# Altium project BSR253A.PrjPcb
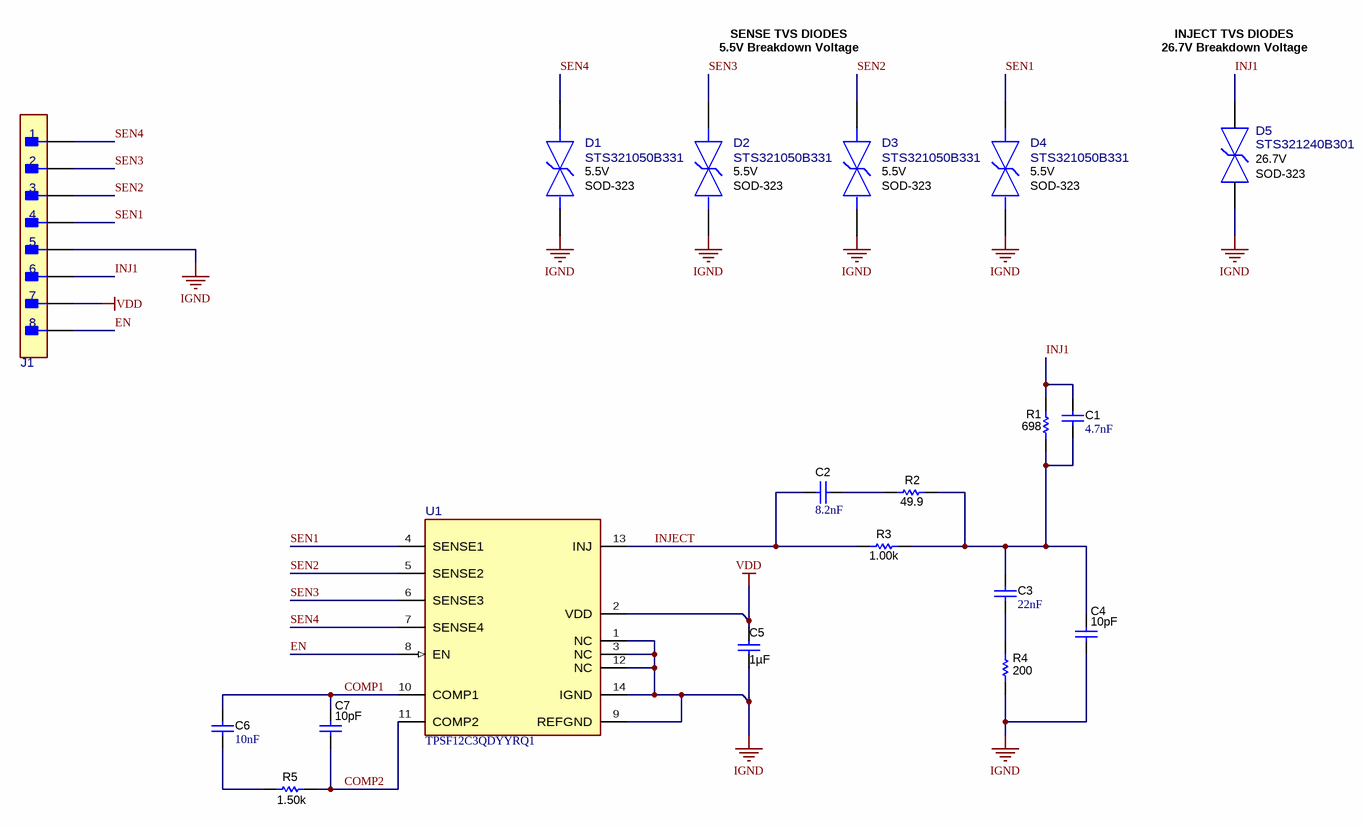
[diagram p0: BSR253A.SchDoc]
DrawnBy: Tony Jacobs; PCB_Rev: A; PRJ_Customer: TBD; PRJ_Engineer: Timothy Hegarty; PRJ_Number: BSR253; PRJ_Title: TPSF12C3QEVM; SCH_Rev: A; TechSupport: TBD; TID: N/A; title: Daughter Card Schematic
2 sheets, 29 parts. Net scope: global (net labels, ports and power ports of the same name join across sheets).
Board file: BSR253A.PcbDoc
Sheets:
  BSR253A.SchDoc
  BSR253A HW.SchDoc

## Sheet BSR253A.SchDoc: Daughter Card Schematic
size A3; Date: Not shown in title block; ApprovedBy: Not shown in title block; CheckedBy: Not shown in title block; Author: Not shown in title block; CompanyName: Not shown in title block; DrawnBy: Tony Jacobs; Engineer: Not shown in title block; Organization: Not shown in title block; Address1: Not shown in title block; Address2: Not shown in title block; Address3: Not shown in title block; Address4: Not shown in title block; DocumentNumber: 1; Revision: Use project parameter SCH_Rev; SheetNumber: 1; SheetTotal: 2; PageSetup: Record=PageOptions¦CenterHorizontal=True¦CenterVertical=True¦PrintScale=0.93¦XCorrection=1.00¦YCorrection=1.00¦PrintKind=0¦BorderSize=5000000¦LeftOffset=0¦BottomOffset=0¦Orientation=2¦PaperLength=1000¦PaperWidth=1000¦Scale=100¦PaperSource=15¦PrintQuality=600¦MediaType=1¦DitherType=10¦PrintScaleMode=1¦PaperKind=Letter

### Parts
C1  Cap_F: 4.7nF  [0603L]  (hidden comment: C0603C472J5RACTU)
C2  Cap_F: 8.2nF  [0603L]  (hidden comment: GCD188R71H822KA01D)
C3  Cap_F: 22nF  [0603L]  (hidden comment: C0603C223K5RACTU)
C4  value 10pF  [0603L]  (hidden comment: CGA3E2C0G1H100D080AA)
C5  Cap_F: 1µF  [0603L]  (hidden comment: CGA3E1X7R1E105K080AC)
C6  Cap_F: 10nF  [0603L]  (hidden comment: C0603X103K5RACTU)
C7  ValueDisplayed: 10pF  [0603L]  (hidden comment: CGA3E2C0G1H100D080AA)
D1  STS321050B331  PackageReference: SOD-323  Breakdown Voltage: 5.5V  [FP-STS321050B331_SOD-323-MFG]
D2  STS321050B331  PackageReference: SOD-323  Breakdown Voltage: 5.5V  [FP-STS321050B331_SOD-323-MFG]
D3  STS321050B331  PackageReference: SOD-323  Breakdown Voltage: 5.5V  [FP-STS321050B331_SOD-323-MFG]
D4  STS321050B331  PackageReference: SOD-323  Breakdown Voltage: 5.5V  [FP-STS321050B331_SOD-323-MFG]
D5  STS321240B301  PackageReference: SOD-323  Breakdown Voltage: 26.7V  [FP-STS321240B301_SOD-323-MFG]
J1  TSW-108-08-G-S-RA  [FP-TSW-108-08-G-S-RA_HDR8-MFG]  (value not drawn)
R1  ValueDisplayed: 698  [0603L]  (hidden comment: CRCW0603698RFKEA)
R2  ValueDisplayed: 49.9  [0603L]  (hidden comment: CRCW060349R9FKEA)
R3  ValueDisplayed: 1.00k  [0603L]  (hidden comment: CRCW06031K00FKEA)
R4  ValueDisplayed: 200  [0603L]  (hidden comment: CRCW0603200RFKEA)
R5  ValueDisplayed: 1.50k  [0603L]  (hidden comment: CRCW06031K50FKEA)
U1  TPSF12C3QDYYRQ1  [DYY0014A-MFG]

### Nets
IGND: C4.1 C5.2 D1.2 D2.2 D3.2 D4.2 D5.2 J1.5 R4.1 U1.1(NC) U1.3(NC) U1.9(REFGND) U1.12(NC) U1.14(IGND)
VDD: C5.1 J1.7 U1.2(VDD)
COMP1: C6.2 C7.2 U1.10(COMP1)
COMP2: C7.1 R5.2 U1.11(COMP2)
EN: J1.8 U1.8(EN)
INJ1: C1.2 D5.1 J1.6 R1.2
INJECT: C2.1 R3.1 U1.13(INJ)
SEN1: D4.1 J1.4 U1.4(SENSE1)
SEN2: D3.1 J1.3 U1.5(SENSE2)
SEN3: D2.1 J1.2 U1.6(SENSE3)
SEN4: D1.1 J1.1 U1.7(SENSE4)
NetC1_1: C1.1 C3.1 C4.2 R1.1 R2.2 R3.2
NetC2_2: C2.2 R2.1
NetC3_2: C3.2 R4.2
NetC6_1: C6.1 R5.1

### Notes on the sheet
- SENSE TVS DIODES
- 5.5V Breakdown Voltage
- INJECT TVS DIODES
- 26.7V Breakdown Voltage

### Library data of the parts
C1 = CMP-0006942-1: CAP, CERM, 4700 pF, 50 V, +/- 5%, X7R, 0603; Manufacturer: Kemet; TaMin_C: -55°C; Polarized: N; SizeAreaWB_mm2: 4.68; Value1: Unknown; U/M: EA; Value: 4700pF; TaMax_C: 125°C; SizeZ_mm: 1; SizeX_mm: 1.6; SizeY_mm: 0.8; Cap_Case: 0603; Value2: 50V; SizeArea_mm2: 1.28; AEC Category: Q200
C2 = CMP-0007123-4: CAP, CERM, 8200 pF, 50 V, +/- 10%, X7R, AEC-Q200 Grade 1, 0603; Manufacturer: MuRata; TaMin_C: -55°C; Polarized: N; SizeAreaWB_mm2: 4.68; Value1: Unknown; U/M: EA; Value: 8200pF; TaMax_C: 125°C; SizeZ_mm: 1; SizeX_mm: 1.6; SizeY_mm: 0.8; Cap_Case: 0603; Value2: 50V; SizeArea_mm2: 1.28; AEC Qualified: Y; AEC Category: Q200
C3 = CMP-0006901-4: CAP, CERM, 0.022 uF, 50 V, +/- 10%, X7R, 0603; Manufacturer: Kemet; TaMin_C: -55°C; Polarized: N; Value1: Unknown; U/M: EA; TaMax_C: 125°C; SizeAreaWB_mm2: 4.68; SizeZ_mm: 1; SizeX_mm: 1.6; SizeY_mm: 0.8; Cap_Case: 0603; Value2: 50V; SizeArea_mm2: 1.28; AEC Category: Q200
C4 = CMP-0007069-4: CAP, CERM, 10 pF, 50 V, +/- 5%, C0G/NP0, AEC-Q200 Grade 1, 0603; Manufacturer: TDK; TaMin_C: -55°C; Polarized: N; SizeAreaWB_mm2: 4.68; Value1: Unknown; U/M: EA; TaMax_C: 125°C; SizeZ_mm: 1; SizeX_mm: 1.6; SizeY_mm: 0.8; Cap_Case: 0603; Value2: 50V; SizeArea_mm2: 1.28; AEC Qualified: Y; AEC Category: Q200
C5 = CMP-0076705-3: CAP, CERM, 1 µF, 25 V,+/- 10%, X7R, AEC-Q200 Grade 1, 0603; Manufacturer: TDK; SizeAreaWB_mm2: 4.68; SizeArea_mm2: 1.28; AEC Qualified: Y; AEC Category: Q200; Value: 1uF; TaMax_C: 125°C; SizeZ_mm: 1.0; AEC Grade: 1; Polarized: N; TaMin_C: -55°C; VDC_V: 25V; SizeY_mm: 0.8; U/M: EA; SizeX_mm: 1.6; Cap_Case: 1.6x0.8x0.8mm
C6 = CMP-0006978-1: CAP, CERM, 0.01 uF, 50 V, +/- 10%, X7R, 0603; Manufacturer: Kemet; TaMin_C: -55°C; Polarized: N; SizeAreaWB_mm2: 4.68; Value1: Unknown; U/M: EA; Value: 0.01uF; TaMax_C: 125°C; SizeZ_mm: 1; SizeX_mm: 1.6; SizeY_mm: 0.8; Cap_Case: 0603; Value2: 50V; SizeArea_mm2: 1.28; AEC Category: Q200
C7 = CMP-0007069-4: CAP, CERM, 10 pF, 50 V, +/- 5%, C0G/NP0, AEC-Q200 Grade 1, 0603; Manufacturer: TDK; TaMin_C: -55°C; Polarized: N; SizeAreaWB_mm2: 4.68; Value1: Unknown; U/M: EA; Value: 10pF; TaMax_C: 125°C; SizeZ_mm: 1; SizeX_mm: 1.6; SizeY_mm: 0.8; Cap_Case: 0603; Value2: 50V; SizeArea_mm2: 1.28; AEC Qualified: Y; AEC Category: Q200
D1-D4 = CMP-0092592-1: 18V Clamp 22A (8/20µs) Ipp Tvs Diode Surface Mount SOD-323; Manufacturer: Eaton; Cap_F: 33pF; Number Of Channels: 1; SizeZ_mm: 1mm; AEC Qualified: No; Ppk: 400W; VRWM: 5V; TJmax_C: +125°C; Direction: Bidirectional
D5 = CMP-0092593-1: 50V Clamp 8A (8/20µs) Ipp Tvs Diode Surface Mount SOD-323; Manufacturer: Eaton; VRWM: 24V; Ppk: 400W; ValueDisplayed: 40pF; Standoff Height: 0mm; SizeZ_mm: 1mm; Direction: Bidirectional; TJmax_C: +125°C; AEC Qualified: No; Number Of Channels: 1
J1 = CMP-0097195-1: Manufacturer: Samtec; AEC Qualified: No; Conn Gender: Male; SizeZ_mm: 3.15mm; ContactFinish: Gold,Nickel; DUT-Pitch_mm: 2.54mm; Row_Count: 1; Conn Orientation: Right Angle
R1 = CMP-0022555-5: RES, 698, 1%, 0.1 W, AEC-Q200 Grade 0, 0603; Manufacturer: Vishay-Dale; Power_W: 100mW; TempCo: 100 ppm/C; Value_Code: 698R; Value: 698; EIA_Code: E96; SizeX_mm: 1.6; SizeY_mm: 0.8; SizeZ_mm: 1; Value2: 0.1W; SizeArea_mm2: 1.28; AEC Qualified: Y; VDC_V: 75V; AEC Category: Q200; AEC Grade: 0
R2 = CMP-0022448-4: RES, 49.9, 1%, 0.1 W, AEC-Q200 Grade 0, 0603; Manufacturer: Vishay-Dale; Power_W: 100mW; TempCo: 100 ppm/C; Value_Code: 49R9; Value: 49.9; EIA_Code: E96; SizeX_mm: 1.6; SizeY_mm: 0.8; SizeZ_mm: 1; Value2: 0.1W; SizeArea_mm2: 1.28; AEC Qualified: Y; VDC_V: 75V; AEC Category: Q200; AEC Grade: 0
R3 = CMP-0022109-5: RES, 1.00 k, 1%, 0.1 W, AEC-Q200 Grade 0, 0603; Manufacturer: Vishay-Dale; Power_W: 100mW; TempCo: 100 ppm/C; Value_Code: 1k00; Value: 1.00k; EIA_Code: E96; Res_ohm: 1k; SizeX_mm: 1.6; SizeY_mm: 0.8; SizeZ_mm: 1; Value2: 0.1W; SizeArea_mm2: 1.28; AEC Qualified: Y; VDC_V: 75V; AEC Category: Q200; AEC Grade: 0
R4 = CMP-0022201-5: RES, 200, 1%, 0.1 W, AEC-Q200 Grade 0, 0603; Manufacturer: Vishay-Dale; Power_W: 100mW; TempCo: 100 ppm/C; Value_Code: 200R; Value: 200; EIA_Code: E96; SizeX_mm: 1.6; SizeY_mm: 0.8; SizeZ_mm: 1; Value2: 0.1W; SizeArea_mm2: 1.28; AEC Qualified: Y; VDC_V: 75V; AEC Category: Q200; AEC Grade: 0
R5 = CMP-0022126-4: RES, 1.50 k, 1%, 0.1 W, AEC-Q200 Grade 0, 0603; Manufacturer: Vishay-Dale; Power_W: 100mW; TempCo: 100 ppm/C; Value_Code: 1k50; Value: 1.50k; EIA_Code: E96; Res_ohm: 1.5k; SizeX_mm: 1.6; SizeY_mm: 0.8; SizeZ_mm: 1; Value2: 0.1W; SizeArea_mm2: 1.28; AEC Qualified: Y; VDC_V: 75V; AEC Category: Q200; AEC Grade: 0
U1 = CMP-0092526-6: Stand Alone Active EMI Filter; Manufacturer: Texas Instruments; AEC Category: Q200; Standoff Height: 0mm; SizeZ_mm: 1.1mm; TJmax_C: +150°C; CompType: IC

## Sheet BSR253A HW.SchDoc: Daughter Card Schematic
size 431 x 279 mm; Date: Not shown in title block; ApprovedBy: Not shown in title block; CheckedBy: Not shown in title block; Author: Not shown in title block; CompanyName: Not shown in title block; DrawnBy: Tony Jacobs; Engineer: Not shown in title block; Organization: Not shown in title block; Address1: Not shown in title block; Address2: Not shown in title block; Address3: Not shown in title block; Address4: Not shown in title block; DocumentNumber: 2; Revision: Use project parameter SCH_Rev; SheetNumber: 2; SheetTotal: 2; PageSetup: Record=PageOptions¦CenterHorizontal=True¦CenterVertical=True¦PrintScale=1.00¦XCorrection=1.00¦YCorrection=1.00¦PrintKind=0¦BorderSize=5000000¦LeftOffset=0¦BottomOffset=0¦Orientation=2¦PaperLength=1000¦PaperWidth=1000¦Scale=100¦PaperSource=15¦PrintQuality=600¦MediaType=1¦DitherType=10¦PaperKind=Letter¦PrintScaleMode=1
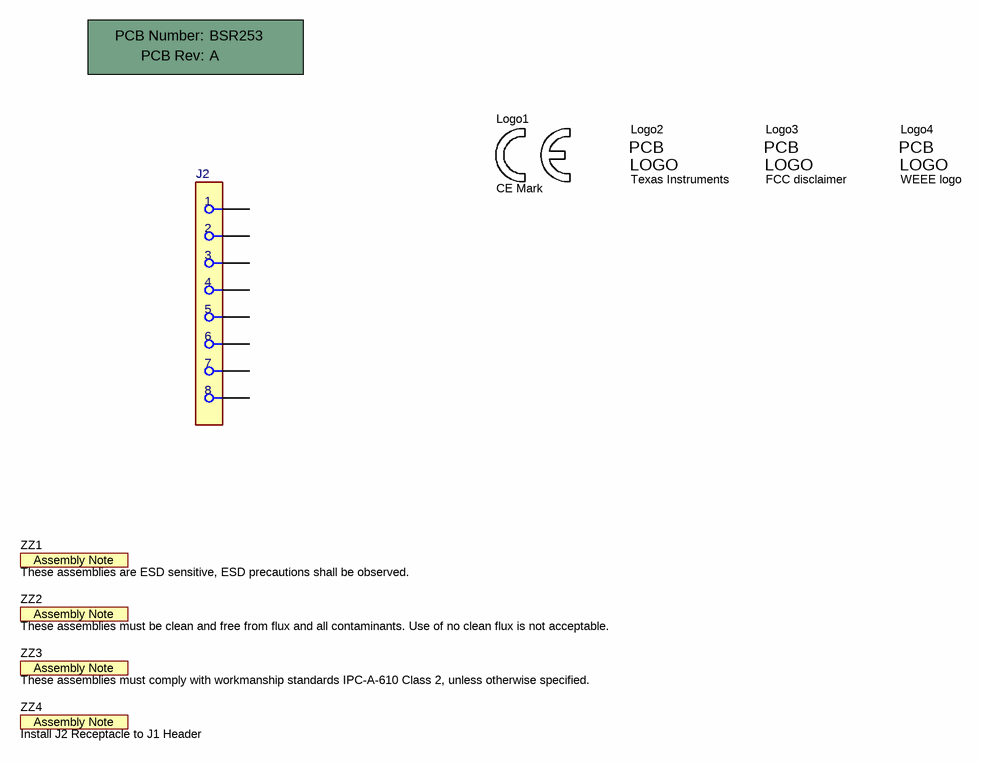
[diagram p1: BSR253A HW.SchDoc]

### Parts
!PCB1  Printed Circuit Board  (value not drawn)  (mechanical)
J2  SSW-108-01-G-S  [FP-SSW-108-01-G-S_CONN_RCPT8-MFG]  (value not drawn)  (mechanical)
Logo1  CE Mark  [CE_Mark_5mm]  (no BOM)
Logo2  Texas Instruments  [TI_Symbol_Overlay_Small]  (no BOM)
Logo3  FCC disclaimer  [FCC_disclaimer]  (no BOM)
Logo4  WEEE logo  [WEEE_Minimum]  (no BOM)
ZZ1  These assemblies are ESD sensitive, ESD precautions shall be observed.  [AssemblyNote]  (no BOM)
ZZ2  These assemblies must be clean and free from flux and all contaminants. Use of no clean flux is not acceptable.  [AssemblyNote]  (no BOM)
ZZ3  These assemblies must comply with workmanship standards IPC-A-610 Class 2, unless otherwise specified.  [AssemblyNote]  (no BOM)
ZZ4  Install J2 Receptacle to J1 Header  [AssemblyNote]  (no BOM)

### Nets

Not connected (* = marked no-connect by the designer): J2 1 2 3 4 5 6 7 8

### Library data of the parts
!PCB1 = CMP-0003618-2: Manufacturer: Any; PartNumber: BSR253
J2 = CMP-0091369-1: CONN RCPT 8POS 0.1 GOLD PCB; Manufacturer: Samtec; SizeZ_mm: 8.64mm; Import Ts: 1521856010; Current_A: 4.7A; DUT-Pitch_mm: 2.54mm; Ciiva Ids: 678528; AEC Qualified: No; ContactFinish: Gold,Nickel; Conn Gender: Female; Voltage_V: 655V; Is Female: yes; Row_Count: 1; Conn Orientation: Vertical
Logo1 = CMP-0074844-1: SymbolCreator: a0412235
Logo2 = CMP-0074838-1: Texas Instrument Corporate Signature; SymbolCreator: a0412235; Lib Reference: TI_Logo
Logo3 = CMP-0074847-1: FCC_disclaimer
Logo4 = CMP-0074769-1
ZZ1 = CMP-0077236-1
ZZ2 = CMP-0077237-1
ZZ3 ZZ4 = CMP-0077238-1

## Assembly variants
001: not fitted C4 D1 D2 D3 D4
